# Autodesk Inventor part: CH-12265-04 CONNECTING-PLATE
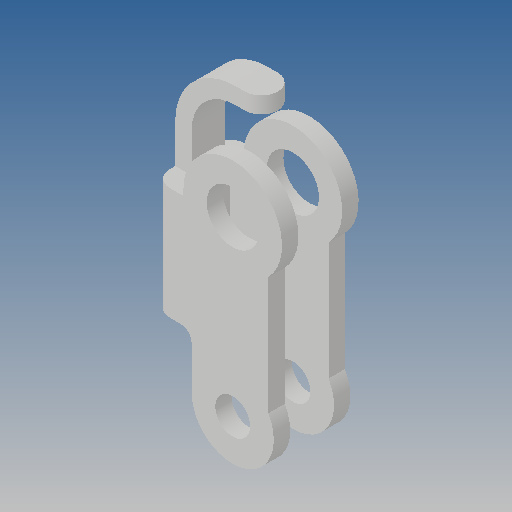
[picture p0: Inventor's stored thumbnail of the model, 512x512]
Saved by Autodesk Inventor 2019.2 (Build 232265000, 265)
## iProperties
Created: 2012-09
Part Number: CH-12265-04 CONNECTING-PLATE
Material: Ogólny
Document SubType Name: Modeling
Designer: CADENGINEERING4
Density: 1 g/cm^3
Appearance: Domyślna
Author: CADENGINEERING4
Revision Number: ÈÎºÎ
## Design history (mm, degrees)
feature "Ô²½Ç3"
node "Bryła1"
